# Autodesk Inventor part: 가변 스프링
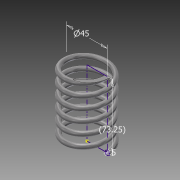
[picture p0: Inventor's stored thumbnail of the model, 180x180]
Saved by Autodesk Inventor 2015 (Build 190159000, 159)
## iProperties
Created: 2015-10
Part Number: 가변 스프링
Material: 강철, 연강
Document SubType Name: Modeling
Designer: youjin17
Mass: 128.859 g
Surface Area: 133.055 cm^2
Volume: 16.4151 cm^3
Density: 7.85 g/cm^3
Appearance: 반연마
Author: youjin17
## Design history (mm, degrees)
sketch "스케치1"
  geometry: L1 (0, 0)-(-22.5, 0); L2 (-22.5, 0)-(-22.5, 73.25); L3 (-22.5, 73.25)-(0, 73.25); L4 (0, 73.25)-(0, 0); C1 r 2.5 at (-22.5, 0); 1 further point
  constraints: 8 end point, 2 coincident, 2 parallel, 1 centre point, 1 horizontal, 1 perpendicular
  dimensions: "d0" = 73.25 distance of L1.end L2.end (derived); "d1" = 45 diameter of L2 L4; "d2" = 5 diameter of C1
feature "코일1" sketch "스케치1" pitch "d3" = 10; turns "d5" = 6; dims "d4" = 73.25 (= d0), "d6" = 0, angle "d7" = 90 deg, angle "d8" = 90 deg, "d9" = 0, "d10" = 0
sketch "스케치2"
  geometry: L1 (25, 0)-(20, 0) reference; 1 further point
  constraints: 1 horizontal alignment
extrude "돌출1" cut sketch "스케치2" stored distance "d11" = 10; taper "d12" = 0 deg
node "작업 평면1"
sketch "스케치3"
  geometry: L1 (-25, 0)-(-20, 0) reference; 1 further point
  constraints: 1 horizontal alignment
extrude "돌출2" cut sketch "스케치3" stored distance "d13" = 10; taper "d14" = 0 deg
node "솔리드1"
node "절단 모서리 투영1"
node "절단 모서리 투영2"
